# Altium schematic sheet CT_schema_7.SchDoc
size 287 x 160 mm
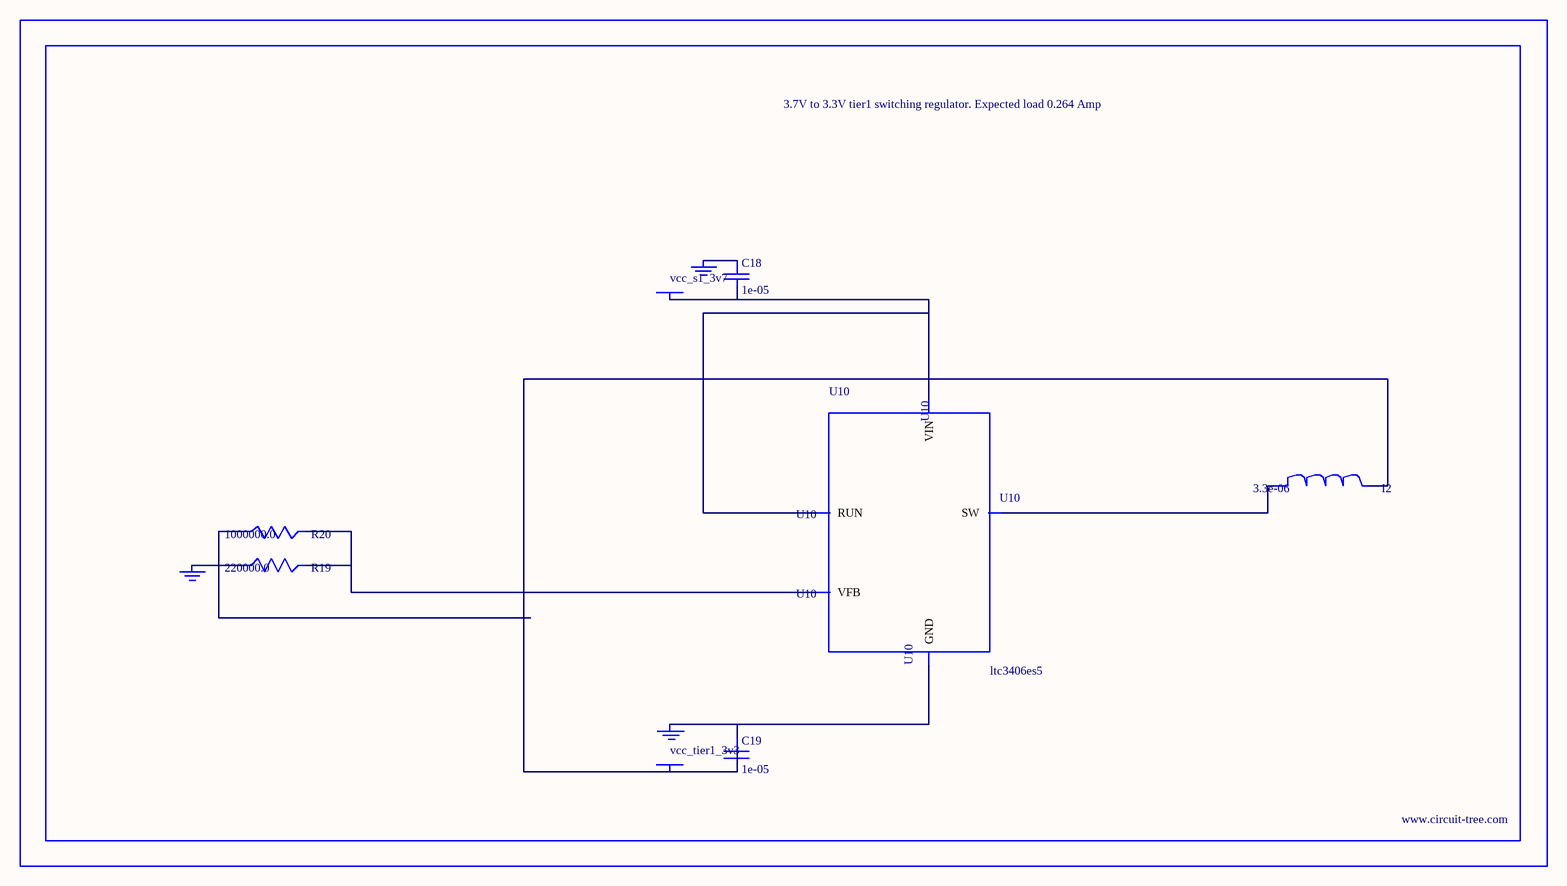
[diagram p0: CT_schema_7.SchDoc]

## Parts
BORDER6  (no value)
C18  1e-05  [C0805]
C19  1e-05  [C0805]
GND_INSTANCE_6_0  (no value)
GND_INSTANCE_6_1  (no value)
GND_INSTANCE_6_2  (no value)
I2  3.3e-06  [L0806]
POWER_INSTANCE_6_0  vcc_tier1_3v3
POWER_INSTANCE_6_1  vcc_s1_3v7
R19  220000.0  [R0603]
R20  1000000.0  [R0603]
U10  ltc3406es5  [TSOT-23-5]

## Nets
NetC18_1: C18.1 GND_INSTANCE_6_1.0(GND)
NetC18_2: C18.2 POWER_INSTANCE_6_1.0(PWR) U10.1(RUN) U10.4(VIN)
NetC19_1: C19.1 GND_INSTANCE_6_0.0(GND) U10.2(GND)
NetC19_2: C19.2 I2.2 POWER_INSTANCE_6_0.0(PWR) R20.1
NetGND_INSTANCE_6_2_0: GND_INSTANCE_6_2.0(GND) R19.1
NetI2_1: I2.1 U10.3(SW)
NetR19_2: R19.2 R20.2 U10.5(VFB)

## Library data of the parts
BORDER6 = BORDER_PAGE6
C18 C19 = C0805C106K8RACTU
GND_INSTANCE_6_0-GND_INSTANCE_6_2 = GND
I2 = L0806C3R3MDWIT
POWER_INSTANCE_6_0 POWER_INSTANCE_6_1 = PWR
R19 = RC0603JR-07220KL
R20 = RC0603JR-071ML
